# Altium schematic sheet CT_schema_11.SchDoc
size 388 x 278 mm
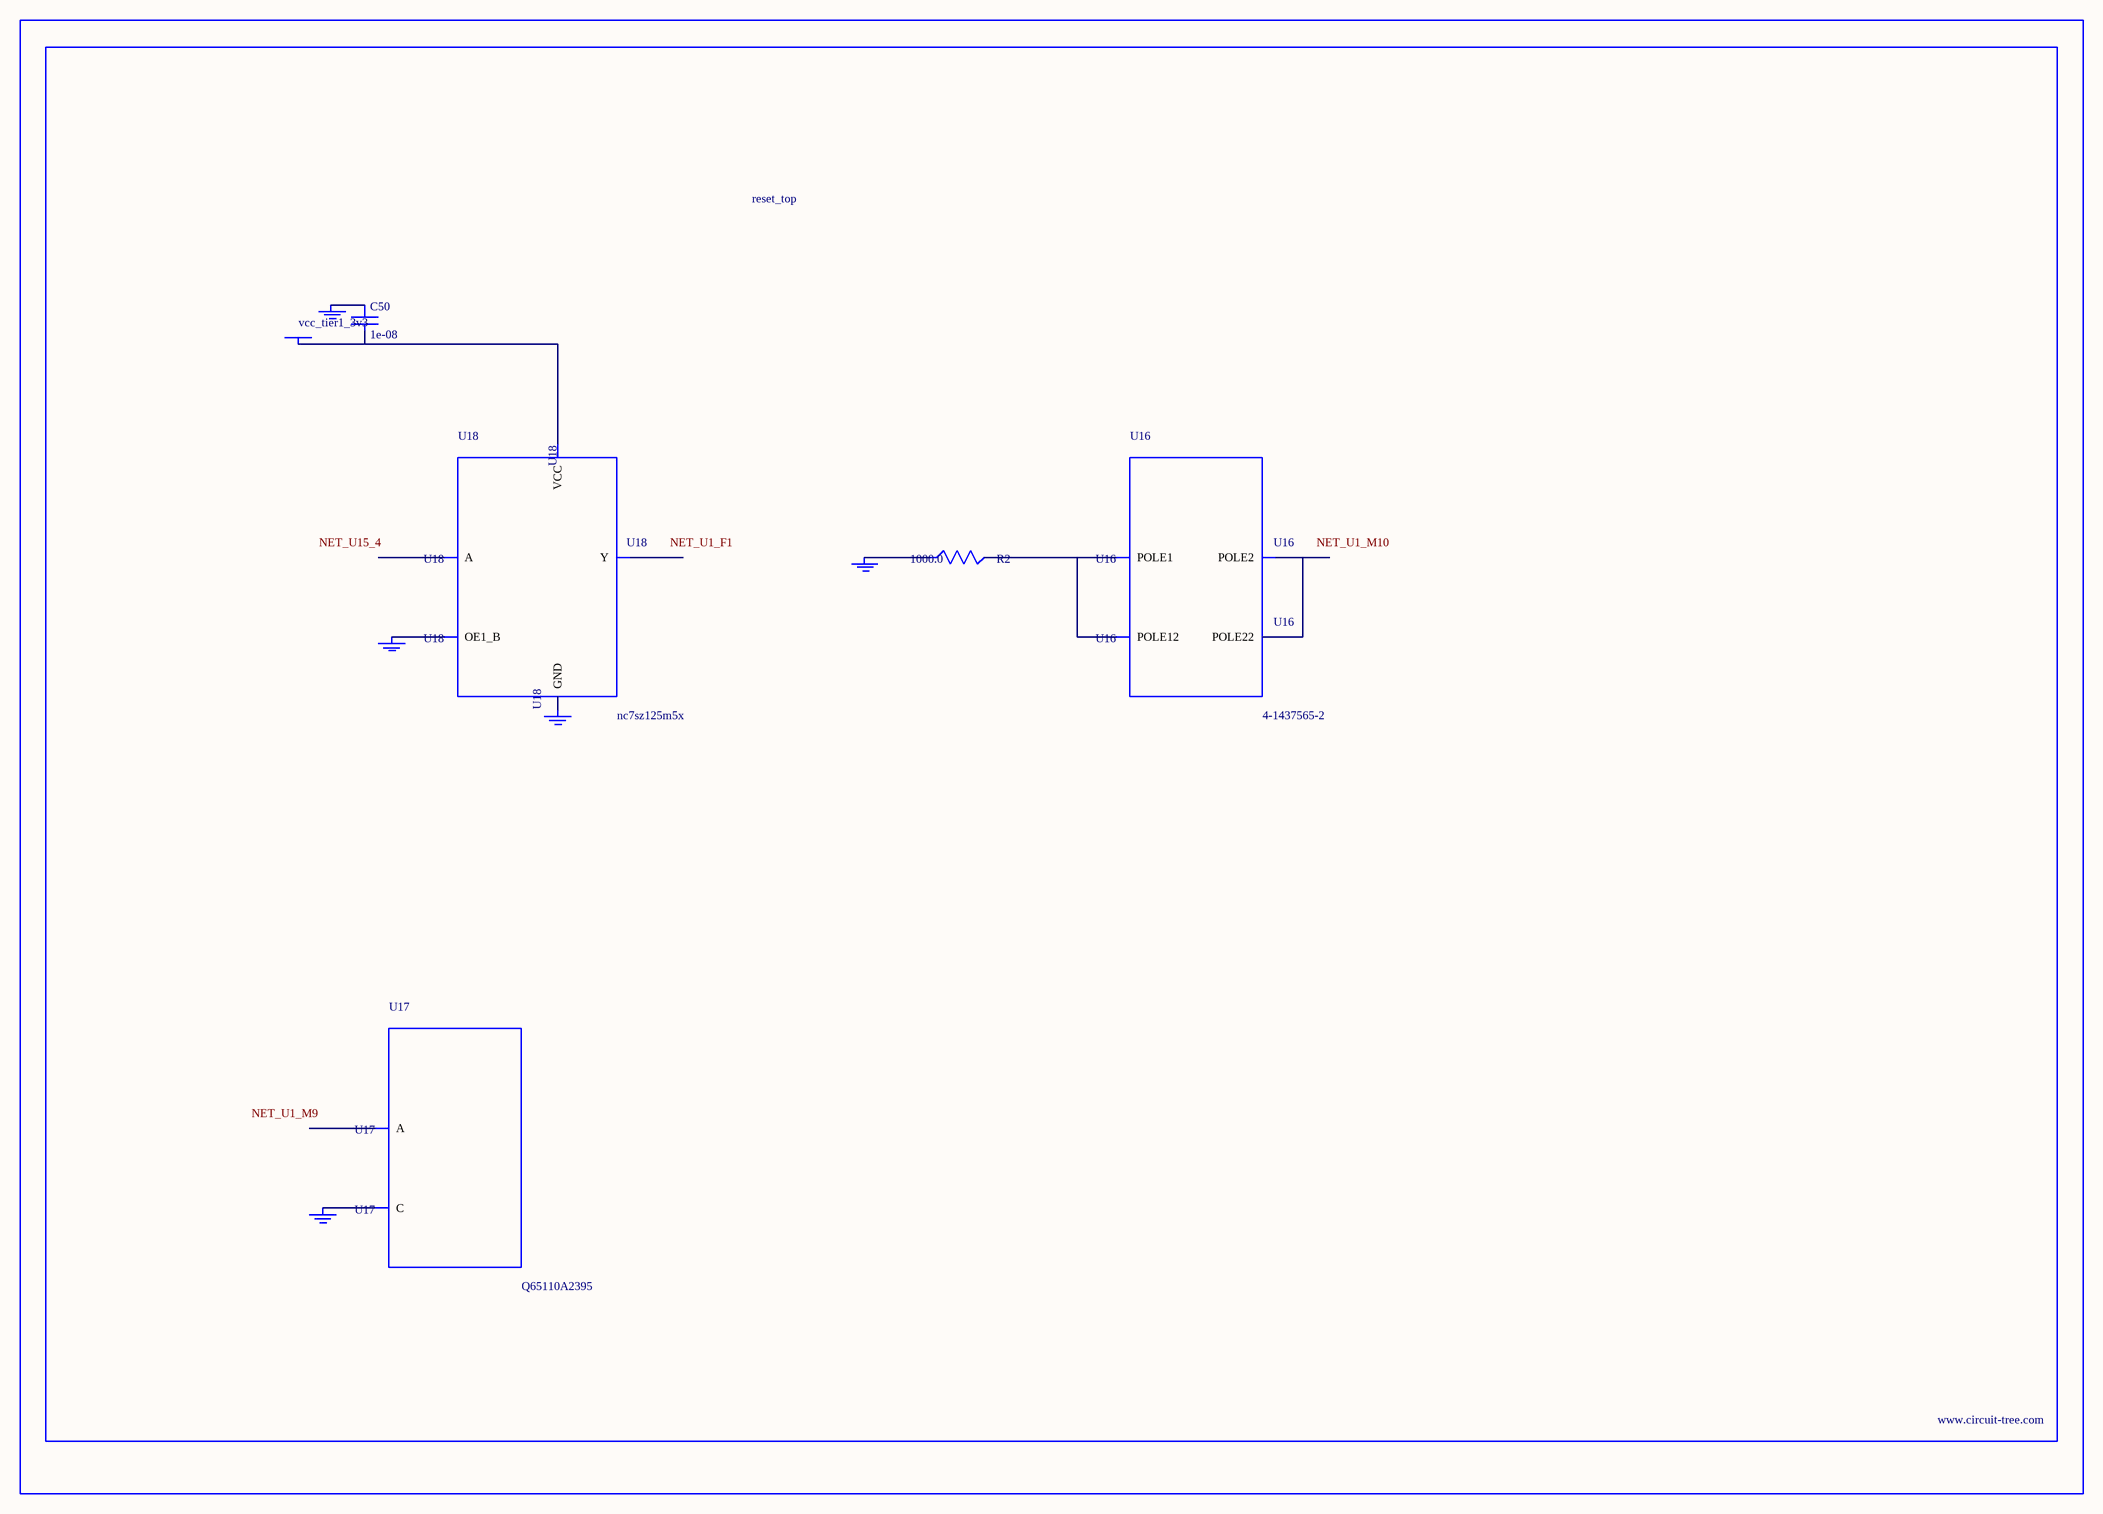
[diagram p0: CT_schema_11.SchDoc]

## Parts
BORDER10  (no value)
C50  1e-08  [C0402]
GND_INSTANCE_10_0  (no value)
GND_INSTANCE_10_1  (no value)
GND_INSTANCE_10_2  (no value)
GND_INSTANCE_10_3  (no value)
GND_INSTANCE_10_4  (no value)
POWER_INSTANCE_10_0  vcc_tier1_3v3
R2  1000.0  [R0603]
U16  4-1437565-2  [SW_4-1437565-2]
U17  Q65110A2395  [LGM67K-G1J2-24-Z]
U18  nc7sz125m5x  [NC7SZ125M5X]

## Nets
NetC50_1: C50.1 GND_INSTANCE_10_2.0(GND)
NetC50_2: C50.2 POWER_INSTANCE_10_0.0(PWR) U18.5(VCC)
NetGND_INSTANCE_10_0_0: GND_INSTANCE_10_0.0(GND) R2.1
NetGND_INSTANCE_10_1_0: GND_INSTANCE_10_1.0(GND) U17.C
NetGND_INSTANCE_10_3_0: GND_INSTANCE_10_3.0(GND) U18.1(OE1_B)
NetGND_INSTANCE_10_4_0: GND_INSTANCE_10_4.0(GND) U18.3(GND)
NetR2_2: R2.2 U16.1(POLE1) U16.2(POLE12)
NetU16_3: U16.3(POLE2) U16.4(POLE22)

Not connected (* = marked no-connect by the designer): U17 A; U18 2(A) 4(Y)

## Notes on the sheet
- Labels drawn without touching a wire or pin: NET_U1_F1, NET_U1_M9, NET_U1_M10, NET_U15_4

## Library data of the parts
BORDER10 = BORDER_PAGE10
C50 = C0402C103K3RAC
GND_INSTANCE_10_0-GND_INSTANCE_10_4 = GND
POWER_INSTANCE_10_0 = PWR
R2 = RC0603JR-071KL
